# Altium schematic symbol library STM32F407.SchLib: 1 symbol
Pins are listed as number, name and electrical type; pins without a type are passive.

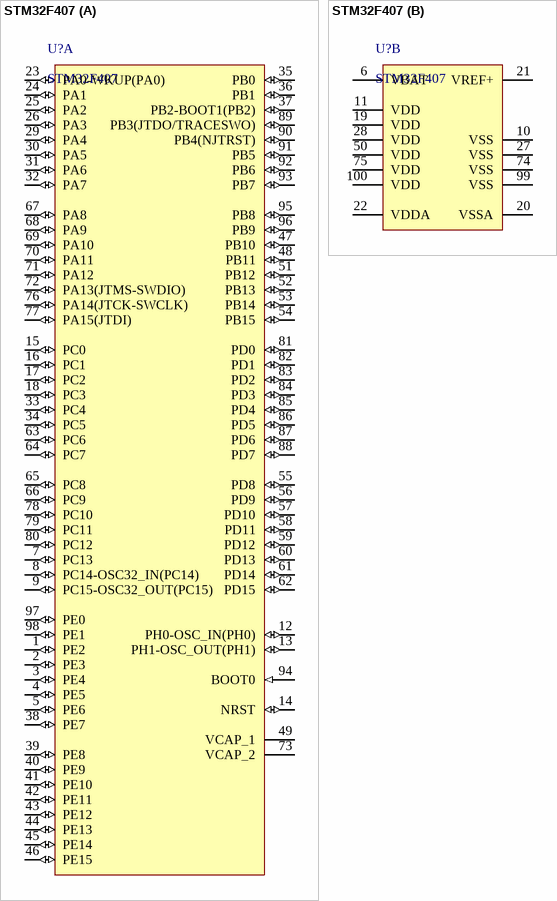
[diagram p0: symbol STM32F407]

## STM32F407
designator U?
STM32F407 32 bit Microcontroller
footprint STM-LQFP100_N (Thin QFP, 100-Leads, Body 14x14mm, Pitch 0.5mm, IPC Medium Density)
part A pins: 1 PE2 (io) "PE2/TRACECLK/FSMC_A23/ETH_MII_TXD3/EVENTOUT", 2 PE3 (io) "PE3/TRACED0/FSMC_A19/EVENTOUT", 3 PE4 (io) "PE4/TRACED1/FSMC_A20/DCMI_D4/EVENTOUT", 4 PE5 (io) "PE5/TRACED2/FSMC_A21/TIM9_CH1/DCMI_D6/EVENTOUT", 5 PE6 (io) "PE6/TRACED3/FSMC_A22/TIM9_CH2/DCMI_D7/EVENTOUT", 7 PC13 (io) "PC13/EVENTOUT/RTC_OUT,RTC_TAMP1,RTC_TS", 8 PC14-OSC32_IN(PC14) (io) "PC14-OSC32_IN(PC14)/EVENTOUT/OSC32_IN", 9 PC15-OSC32_OUT(PC15) (io) "PC15-OSC32_OUT(PC15)/EVENTOUT/OSC32_OUT", 12 PH0-OSC_IN(PH0) (io) "PH0-OSC_IN(PH0)/EVENTOUT/OSC_IN", 13 PH1-OSC_OUT(PH1) (io) "PH1-OSC_OUT(PH1)/EVENTOUT/OSC_OUT", 14 NRST (io), 15 PC0 (io) "PC0/OTG_HS_ULPI_STP/EVENTOUT/ADC123_IN10", 16 PC1 (io) "PC1/ETH_MDC/EVENTOUT/ADC123_IN11", 17 PC2 (io) "PC2/SPI2_MISO/OTG_HS_ULPI_DIR/ETH_MII_TXD2/I2S2ext_SD/EVENTOUT/ADC123_IN12", 18 PC3 (io) "PC3/SPI2_MOSI/I2S2_SD/OTG_HS_ULPI_NXT/ETH_MII_TX_CLK/EVENTOUT/ADC123_IN13", 23 PA0-WKUP(PA0) (io) "PA0-WKUP(PA0)/USART2_CTS/UART4_TX/ETH_MII_CRS/TIM2_CH1_ETR/TIM5_CH1/TIM8_ETR/EVENTOUT/ADC123_IN0/WKUP", 24 PA1 (io) "PA1/USART2_RTS/UART4_RX/ETH_RMII_REF_CLK/ETH_MII_RX_CLK/TIM5_CH2/TIM2_CH2/EVENTOUT/ADC123_IN1", 25 PA2 (io) "PA2/USART2_TX/TIM5_CH3/TIM9_CH1/TIM2_CH3/ETH_MDIO/EVENTOUT/ADC123_IN2", 26 PA3 (io) "PA3/USART2_RX/TIM5_CH4/TIM9_CH2/TIM2_CH4/OTG_HS_ULPI_D0/ETH_MII_COL/EVENTOUT/ADC123_IN3", 29 PA4 (io) "PA4/SPI1_NSS/SPI3_NSS/USART2_CK/DCMI_HSYNC/OTG_HS_SOF/I2S3_WS/EVENTOUT/ADC12_IN4/DAC_OUT1", 30 PA5 (io) "PA5/SPI1_SCK/OTG_HS_ULPI_CK/TIM2_CH1_ETR/TIM8_CH1N/EVENTOUT/ADC12_IN5/DAC_OUT2", 31 PA6 (io) "PA6/SPI1_MISO/TIM8_BKIN/TIM13_CH1/DCMI_PIXCLK/TIM3_CH1/TIM1_BKIN/EVENTOUT/ADC12_IN6", 32 PA7 (io) "PA7/SPI1_MOSI/TIM8_CH1N/TIM14_CH1/TIM3_CH2/ETH_MII_RX_DV/TIM1_CH1N/ETH_RMII_CRS_DV/EVENTOUT/ADC12_IN7", 33 PC4 (io) "PC4/ETH_RMII_RX_D0/ETH_MII_RX_D0/EVENTOUT/ADC12_IN14", 34 PC5 (io) "PC5/ETH_RMII_RX_D1/ETH_MII_RX_D1/EVENTOUT/ADC12_IN15", 35 PB0 (io) "PB0/TIM3_CH3/TIM8_CH2N/OTG_HS_ULPI_D1/ETH_MII_RXD2/TIM1_CH2N/EVENTOUT/ADC12_IN8", 36 PB1 (io) "PB1/TIM3_CH4/TIM8_CH3N/OTG_HS_ULPI_D2/ETH_MII_RXD3/TIM1_CH3N/EVENTOUT/ADC12_IN9", 37 PB2-BOOT1(PB2) (io) "PB2-BOOT1(PB2)/EVENTOUT", 38 PE7 (io) "PE7/FSMC_D4/TIM1_ETR/EVENTOUT", 39 PE8 (io) "PE8/FSMC_D5/TIM1_CH1N/EVENTOUT", 40 PE9 (io) "PE9/FSMC_D6/TIM1_CH1/EVENTOUT", 41 PE10 (io) "PE10/FSMC_D7/TIM1_CH2N/EVENTOUT", 42 PE11 (io) "PE11/FSMC_D8/TIM1_CH2/EVENTOUT", 43 PE12 (io) "PE12/FSMC_D9/TIM1_CH3N/EVENTOUT", 44 PE13 (io) "PE13/FSMC_D10/TIM1_CH3/EVENTOUT", 45 PE14 (io) "PE14/FSMC_D11/TIM1_CH4/EVENTOUT", 46 PE15 (io) "PE15/FSMC_D12/TIM1_BKIN/EVENTOUT", 47 PB10 (io) "PB10/SPI2_SCK/I2S2_CK/I2C2_SCL/USART3_TX/OTG_HS_ULPI_D3/ETH_MII_RX_ER/TIM2_CH3/EVENTOUT", 48 PB11 (io) "PB11/I2C2_SDA/USART3_RX/OTG_HS_ULPI_D4/ETH_RMII_TX_EN/ETH_MII_TX_EN/TIM2_CH4/EVENTOUT", 49 VCAP_1 (power), 51 PB12 (io) "PB12/SPI2_NSS/I2S2_WS/I2C2_SMBA/USART3_CK/TIM1_BKIN/CAN2_RX/OTG_HS_ULPI_D5/ETH_RMII_TXD0/ETH_MII_TXD0/OTG_HS_ID/EVENTOUT", 52 PB13 (io) "PB13/SPI2_SCK/I2S2_CK/USART3_CTS/TIM1_CH1N/CAN2_TX/OTG_HS_ULPI_D6/ETH_RMII_TXD1/ETH_MII_TXD1/EVENTOUT/OTG_HS_VBUS", 53 PB14 (io) "PB14/SPI2_MISO/TIM1_CH2N/TIM12_CH1/OTG_HS_DM/USART3_RTS/TIM8_CH2N/I2S2ext_SD/EVENTOUT", 54 PB15 (io) "PB15/SPI2_MOSI/I2S2_SD/TIM1_CH3N/TIM8_CH3N/TIM12_CH2/OTG_HS_DP/EVENTOUT/RTC_REFIN", 55 PD8 (io) "PD8/FSMC_D13/USART3_TX/EVENTOUT", 56 PD9 (io) "PD9/FSMC_D14/USART3_RX/EVENTOUT", 57 PD10 (io) "PD10/FSMC_D15/USART3_CK/EVENTOUT", 58 PD11 (io) "PD11/FSMC_CLE/FSMC_A16/USART3_CTS/EVENTOUT", 59 PD12 (io) "PD12/FSMC_ALE/FSMC_A17/TIM4_CH1/USART3_RTS/EVENTOUT", 60 PD13 (io) "PD13/FSMC_A18/TIM4_CH2/EVENTOUT", 61 PD14 (io) "PD14/FSMC_D0/TIM4_CH3/EVENTOUT", 62 PD15 (io) "PD15/FSMC_D1/TIM4_CH4/EVENTOUT", 63 PC6 (io) "PC6/I2S2_MCK/TIM8_CH1/SDIO_D6/USART6_TX/DCMI_D0/TIM3_CH1/EVENTOUT", 64 PC7 (io) "PC7/I2S3_MCK/TIM8_CH2/SDIO_D7/USART6_RX/DCMI_D1/TIM3_CH2/EVENTOUT", 65 PC8 (io) "PC8/TIM8_CH3/SDIO_D0/TIM3_CH3/USART6_CK/DCMI_D2/EVENTOUT", 66 PC9 (io) "PC9/I2S_CKIN/MCO2/TIM8_CH4/SDIO_D1/I2C3_SDA/DCMI_D3/TIM3_CH4/EVENTOUT", 67 PA8 (io) "PA8/MCO1/USART1_CK/TIM1_CH1/I2C3_SCL/OTG_FS_SOF/EVENTOUT", 68 PA9 (io) "PA9/USART1_TX/TIM1_CH2/I2C3_SMBA/DCMI_D0/EVENTOUT/OTG_FS_VBUS", 69 PA10 (io) "PA10/USART1_RX/TIM1_CH3/OTG_FS_ID/DCMI_D1/EVENTOUT", 70 PA11 (io) "PA11/USART1_CTS/CAN1_RX/TIM1_CH4/OTG_FS_DM/EVENTOUT", 71 PA12 (io) "PA12/USART1_RTS/CAN1_TX/TIM1_ETR/OTG_FS_DP/EVENTOUT", 72 PA13(JTMS-SWDIO) (io) "PA13(JTMS-SWDIO)/JTMS-SWDIO/EVENTOUT", 73 VCAP_2 (power), 76 PA14(JTCK-SWCLK) (io) "PA14(JTCK-SWCLK)/JTCK-SWCLK/EVENTOUT", 77 PA15(JTDI) (io) "PA15(JTDI)/JTDI/SPI3_NSS/I2S3_WS/TIM2_CH1_ETR/SPI1_NSS/EVENTOUT", 78 PC10 (io) "PC10/SPI3_SCK/I2S3_CK/UART4_TX/SDIO_D2/DCMI_D8/USART3_TX/EVENTOUT", 79 PC11 (io) "PC11/UART4_RX/SPI3_MISO/SDIO_D3/DCMI_D4/USART3_RX/I2S3ext_SD/EVENTOUT", 80 PC12 (io) "PC12/UART5_TX/SDIO_CK/DCMI_D9/SPI3_MOSI/I2S3_SD/USART3_CK/EVENTOUT", 81 PD0 (io) "PD0/FSMC_D2/CAN1_RX/EVENTOUT", 82 PD1 (io) "PD1/FSMC_D3/CAN1_TX/EVENTOUT", 83 PD2 (io) "PD2/TIM3_ETR/UART5_RX/SDIO_CMD/DCMI_D11/EVENTOUT", 84 PD3 (io) "PD3/FSMC_CLK/USART2_CTS/EVENTOUT", 85 PD4 (io) "PD4/FSMC_NOE/USART2_RTS/EVENTOUT", 86 PD5 (io) "PD5/FSMC_NWE/USART2_TX/EVENTOUT", 87 PD6 (io) "PD6/FSMC_NWAIT/USART2_RX/EVENTOUT", 88 PD7 (io) "PD7/USART2_CK/FSMC_NE1/FSMC_NCE2/EVENTOUT", 89 PB3(JTDO/TRACESWO) (io) "PB3(JTDO/TRACESWO)/JTDO/TRACESWO/SPI3_SCK/I2S3_CK/TIM2_CH2/SPI1_SCK/EVENTOUT", 90 PB4(NJTRST) (io) "PB4(NJTRST)/NJTRST/SPI3_MISO/TIM3_CH1/SPI1_MISO/I2S3ext_SD/EVENTOUT", 91 PB5 (io) "PB5/I2C1_SMBA/CAN2_RX/OTG_HS_ULPI_D7/ETH_PPS_OUT/TIM3_CH2/SPI1_MOSI/SPI3_MOSI/DCMI_D10/I2S3_SD/EVENTOUT", 92 PB6 (io) "PB6/I2C1_SCL/TIM4_CH1/CAN2_TX/DCMI_D5/USART1_TX/EVENTOUT", 93 PB7 (io) "PB7/I2C1_SDA/FSMC_NL/DCMI_VSYNC/USART1_RX/TIM4_CH2/EVENTOUT", 94 BOOT0 (in) "BOOT0/VPP", 95 PB8 (io) "PB8/TIM4_CH3/SDIO_D4/TIM10_CH1/DCMI_D6/ETH_MII_TXD3/I2C1_SCL/CAN1_RX/EVENTOUT", 96 PB9 (io) "PB9/SPI2_NSS/I2S2_WS/TIM4_CH4/TIM11_CH1/SDIO_D5/DCMI_D7/I2C1_SDA/CAN1_TX/EVENTOUT", 97 PE0 (io) "PE0/TIM4_ETR/FSMC_NBL0/DCMI_D2/EVENTOUT", 98 PE1 (io) "PE1/FSMC_NBL1/DCMI_D3/EVENTOUT"
part B pins: 6 VBAT (power), 10 VSS (power), 11 VDD (power), 19 VDD (power), 20 VSSA (power), 21 VREF+ (power), 22 VDDA (power), 27 VSS (power), 28 VDD (power), 50 VDD (power), 74 VSS (power), 75 VDD (power), 99 VSS (power), 100 VDD (power)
